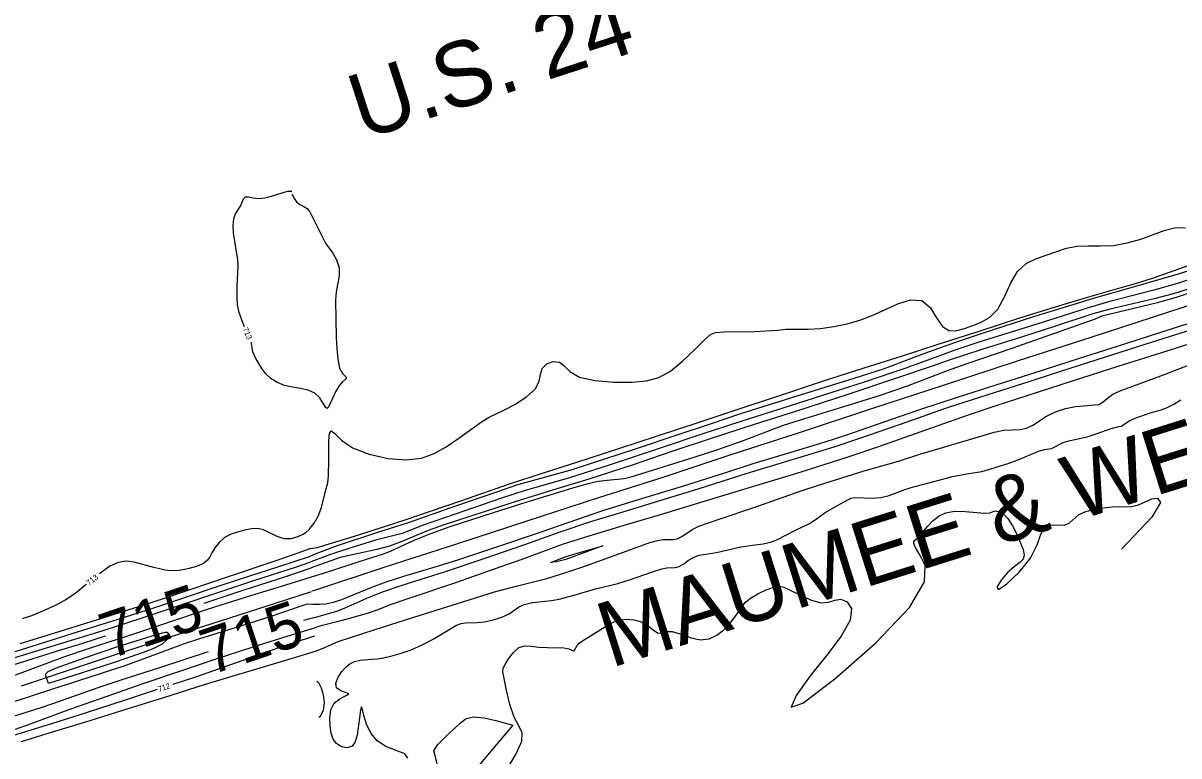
# Model space of a CAD drawing. Extents: x -468548933 to 3387700, y -306089263 to 1207014.
# Drawn here: x 1838882 to 1839713, y 536505 to 537032 of the extents above; entities that cross this region are included whole.
import ezdxf

# ---------------------------------------------------------------- set-up
doc = ezdxf.new("R2010")
doc.units = 0
for name, color, linetype in [('DT_X_Contour_Minor', 7, 'Continuous'), ('Level 14', 7, 'Continuous'), ('Level 19', 7, 'Continuous'), ('Level 40', 7, 'Continuous')]:
    doc.layers.add(name, color=color, linetype=linetype)

msp = doc.modelspace()

# ---------------------------------------------------------------- linework, layer by layer
at = {"layer": 'DT_X_Contour_Minor'}
for points in [[(1839040.98, 536813.8), (1839039.19, 536818.01), (1839037.08, 536824.03), (1839035.91, 536829.55), (1839035.51, 536834.49), (1839035.67, 536842.86), (1839036.26, 536857.84), (1839036.02, 536861.91), (1839034.64, 536870.8), (1839033.04, 536881.32), (1839032.73, 536886.73), (1839033.16, 536891.45), (1839034.49, 536895.05), (1839038, 536900.52), (1839040.26, 536905.73), (1839041.71, 536907.18), (1839043.99, 536907.22), (1839047.12, 536906.53), (1839051, 536906.05), (1839055.49, 536906.49), (1839060.19, 536907.64), (1839071.78, 536911.25), (1839074.81, 536911.39)], [(1839074.93, 536909.12), (1839075.32, 536908.66), (1839076.64, 536906.06), (1839078.31, 536903.58), (1839080.71, 536901.81), (1839083.48, 536900.39), (1839086.01, 536898.74), (1839087.92, 536896.36), (1839099.37, 536873.52), (1839101.8, 536870.42), (1839104.4, 536866.75), (1839107.13, 536861.85), (1839108.89, 536856.24), (1839108.95, 536850.37), (1839106.83, 536838.57), (1839106.37, 536832.92), (1839106.9, 536805.77), (1839107.19, 536798.12), (1839107.9, 536790.35), (1839109.27, 536784.03), (1839111.35, 536780.26), (1839114.26, 536777.3), (1839113.42, 536776.01), (1839111.29, 536774.06), (1839108.69, 536771.1), (1839106.26, 536767), (1839101.41, 536755.82), (1839100.4, 536754.85), (1839099.21, 536755.82), (1839095.01, 536762.54), (1839091.46, 536765.98), (1839086.72, 536768.1), (1839082.13, 536769.09)], [(1839087.34, 536667.91), (1839088.18, 536668.75), (1839091.09, 536672.35), (1839093.97, 536677.39), (1839096.31, 536683.76), (1839099.19, 536695.48), (1839100.43, 536699.91), (1839100.84, 536701.41), (1839101.29, 536706.55), (1839101.45, 536717.89), (1839101.52, 536731.66), (1839101.98, 536736.9), (1839103.22, 536738.98), (1839105.76, 536736.94), (1839110.53, 536732.16), (1839118.62, 536726.62), (1839130.5, 536722.04), (1839144.27, 536719.05), (1839157.47, 536718.03), (1839168.24, 536719.25), (1839177.26, 536722.5), (1839185.86, 536727.48), (1839194.95, 536733.71), (1839211.29, 536745.34), (1839216.76, 536748.63), (1839227.33, 536753.69), (1839235.28, 536757.93), (1839243.66, 536763.29), (1839250.06, 536769.05), (1839252.87, 536774.56), (1839253.69, 536779.54), (1839254.9, 536783.8), (1839258.24, 536787.07), (1839262.89, 536788.81), (1839267.37, 536788.41), (1839270.81, 536785.59), (1839274.86, 536781.51), (1839281.79, 536777.62), (1839293, 536775.12), (1839306.54, 536773.98), (1839319.61, 536773.91), (1839330.11, 536774.76), (1839338.82, 536777.16), (1839347.19, 536781.89), (1839356.2, 536789.25), (1839364.87, 536797.5), (1839371.71, 536804.38), (1839375.95, 536808.24), (1839379.67, 536809.7), (1839385.69, 536810.01), (1839407.63, 536810.45), (1839424.15, 536811.3), (1839430.3, 536811.96), (1839446.38, 536811.93), (1839455.07, 536812.63), (1839464.71, 536813.96), (1839474.39, 536815.95), (1839483.46, 536818.62), (1839492.21, 536821.98), (1839510.74, 536830.3), (1839520.01, 536833.22), (1839527.98, 536832.7), (1839533.94, 536827.58), (1839538.56, 536820.23), (1839542.85, 536813.89), (1839547.54, 536811.01), (1839552.19, 536810.83), (1839558.72, 536812.59), (1839564.7, 536814.62), (1839570.18, 536816.74), (1839576.68, 536820.45), (1839582.81, 536826.52), (1839587.62, 536835.22), (1839591.89, 536844.9), (1839596.78, 536853.43), (1839603.15, 536859.23), (1839610.51, 536862.89), (1839632.22, 536870.38), (1839639.59, 536871.75), (1839647.69, 536872.01), (1839656.53, 536871.88), (1839665.98, 536872.33), (1839675.85, 536874.06), (1839685.57, 536876.79), (1839702.27, 536882.98), (1839709.67, 536885.03), (1839717.78, 536885.23)], [(1839088.05, 536654.13), (1839093.28, 536655.03), (1839099.42, 536656.76), (1839119.97, 536663.21), (1839156.43, 536674.83), (1839174.57, 536680.99), (1839196.38, 536688.56), (1839232.22, 536700.94), (1839261.99, 536710.65), (1839287.94, 536719.11), (1839323.23, 536730.62), (1839367.86, 536745.19), (1839403.81, 536757.02), (1839423.09, 536763.44), (1839455.99, 536774.34), (1839486.57, 536784.19), (1839514.04, 536792.79), (1839539.81, 536801.13), (1839568.56, 536810.46), (1839599.24, 536820.51), (1839632.86, 536830.85), (1839652.16, 536836.58), (1839684.07, 536845.53), (1839694.56, 536849), (1839721.09, 536858.22)], [(1839732.38, 536857.86), (1839712.33, 536851.72), (1839678.35, 536841.85), (1839651.17, 536834.01), (1839633.6, 536828.65), (1839609.2, 536821.09), (1839578.65, 536811.43), (1839554.98, 536803.41), (1839529.99, 536794.42), (1839501.07, 536783.55), (1839479.13, 536776.57), (1839438.19, 536763.75), (1839397.71, 536751.01), (1839376.57, 536743.97), (1839351.9, 536735.79), (1839323.19, 536726.27), (1839275.53, 536710.61), (1839250.45, 536703.59), (1839236.42, 536699.69), (1839222.76, 536695.11), (1839192.75, 536684.6), (1839158.5, 536672.76), (1839136.59, 536665.73), (1839106.13, 536655.6), (1839092.9, 536650.71), (1839088.33, 536648.78)], [(1839743.3, 536855.2), (1839711.86, 536845.01), (1839694.8, 536840.15), (1839663.17, 536832.03), (1839647.78, 536827.48), (1839623.61, 536819.69), (1839595.51, 536810.9), (1839569.87, 536802.82), (1839552.57, 536797.06), (1839537.67, 536791.71), (1839515.8, 536783.7), (1839486.51, 536773.85), (1839462.6, 536766.15), (1839433.37, 536756.94), (1839397.77, 536745.71), (1839369.73, 536736.4), (1839339.74, 536726.36), (1839304.67, 536714.75), (1839273.81, 536704.88), (1839242.84, 536695.91), (1839225.63, 536690.39), (1839192.51, 536679.04), (1839169.32, 536671.09), (1839154.17, 536665.09), (1839142.82, 536662.21), (1839135.1, 536660.22), (1839115.91, 536654.34), (1839102.84, 536649.86), (1839088.54, 536644.59)], [(1839737.01, 536846.82), (1839711.39, 536838.3), (1839696.14, 536834.16), (1839663.45, 536826.37), (1839651.1, 536823.11), (1839623.57, 536814.04), (1839600.5, 536806.5), (1839571.28, 536797.41), (1839547.62, 536789.83), (1839534.88, 536785.3), (1839509.16, 536776.54), (1839475.43, 536765.3), (1839436.47, 536752.64), (1839407.4, 536743.44), (1839377.31, 536733.73), (1839348.29, 536723.97), (1839319.63, 536714.29), (1839288.54, 536704.19), (1839265.62, 536697.07), (1839238.47, 536688.8), (1839213.96, 536680.91), (1839184.45, 536671.21), (1839173.09, 536667.09), (1839154.05, 536659.25), (1839145.16, 536656.02), (1839135.94, 536653.53), (1839109.63, 536647.71), (1839088.76, 536640.4)], [(1839089.1, 536633.79), (1839100.93, 536637.51), (1839123.4, 536644.9), (1839140.76, 536650.3), (1839145.78, 536652.35), (1839162.88, 536660.12), (1839174.98, 536665.09), (1839188.84, 536670.11), (1839219.26, 536679.99), (1839240.29, 536686.5), (1839276.32, 536697.59), (1839288.16, 536701.1), (1839295.16, 536702.63), (1839301.76, 536703.46), (1839313.87, 536704.64), (1839319.8, 536705.97), (1839334.22, 536710.52), (1839364.24, 536719.85), (1839381.43, 536725.41), (1839400.93, 536732.53), (1839428.5, 536742.92), (1839443.82, 536747.87), (1839468.73, 536755.47), (1839498.35, 536764.48), (1839517.71, 536771.34), (1839546.63, 536782.33), (1839560.63, 536787.34), (1839592.34, 536798.05), (1839622.21, 536808.64), (1839652.91, 536819.5), (1839657.6, 536821.56), (1839663.49, 536823.17), (1839697.6, 536831.34), (1839711.19, 536834.95), (1839727.36, 536840.36)], [(1839729.89, 536819.24), (1839698.29, 536809.16), (1839669.22, 536799.83), (1839640.51, 536790.58), (1839610.08, 536780.86), (1839576.7, 536770.23), (1839552.73, 536762.68), (1839526.26, 536754.01), (1839506.2, 536746.95), (1839473.16, 536735.44), (1839458.37, 536730.77), (1839433.8, 536723.31), (1839406.57, 536715.04), (1839386.03, 536708.51), (1839354.92, 536698.65), (1839324.1, 536689.14), (1839298.32, 536681.28), (1839279.68, 536674.98), (1839249.26, 536664.36), (1839225.71, 536656.35), (1839194.83, 536646.07), (1839180.22, 536641.5), (1839155.29, 536634.09), (1839142.5, 536629.96), (1839132.21, 536626.18), (1839110.7, 536617.41), (1839104.7, 536615.49), (1839099.33, 536614.3), (1839094.74, 536613.89), (1839090.11, 536614.04)], [(1839090.61, 536604.46), (1839107.89, 536609.42), (1839113.29, 536611.6), (1839130.64, 536619.23), (1839141.69, 536623.63), (1839153.47, 536627.69), (1839185.48, 536637.69), (1839214, 536647.32), (1839242.42, 536657.02), (1839268.01, 536666.15), (1839289.93, 536673.57), (1839308.47, 536679.3), (1839341.34, 536689.19), (1839367.06, 536697.24), (1839401.64, 536708.13), (1839433.38, 536717.74), (1839465.1, 536727.5), (1839483.4, 536733.55), (1839517.42, 536745.43), (1839547.98, 536756.07), (1839581.11, 536766.7), (1839605.93, 536774.65), (1839628.81, 536781.96), (1839653.49, 536789.88), (1839688.58, 536801.15), (1839722.89, 536812.07)], [(1839732.14, 536805.15), (1839704.34, 536796.31), (1839669, 536785.07), (1839636.87, 536774.79), (1839610.98, 536766.44), (1839581.26, 536756.85), (1839561.43, 536750.17), (1839530.78, 536739.29), (1839496.96, 536727.3), (1839475.48, 536720.2), (1839441.09, 536709.22), (1839422, 536703.41), (1839391.78, 536694.31), (1839358.85, 536684.18), (1839339.15, 536678.11), (1839316.18, 536671.4), (1839288.47, 536663.23), (1839269.37, 536657.04), (1839240.26, 536646.38), (1839214.9, 536637.35), (1839193.26, 536629.84), (1839158.41, 536617.97), (1839146.39, 536613.96), (1839135.94, 536609.87), (1839129.01, 536607.48), (1839111.1, 536602.45), (1839095.14, 536598.26), (1839090.99, 536597)], [(1839082.13, 536769.09), (1839081.18, 536769.29), (1839075.37, 536770.26), (1839069.76, 536771.62), (1839064.58, 536773.6), (1839060.04, 536776.35), (1839056.27, 536779.88), (1839053.23, 536783.8), (1839049.04, 536790.83), (1839046.92, 536795.63), (1839046.28, 536798.79), (1839045.91, 536801.67), (1839045.59, 536802.72)], [(1839091.84, 536580.45), (1839097.49, 536582.55), (1839108.3, 536587.26), (1839134.92, 536596.07), (1839162.75, 536604.87), (1839193.97, 536614.73), (1839220.8, 536623.03), (1839235.3, 536626.9), (1839258.24, 536632.76), (1839271.3, 536636.66), (1839286.45, 536641.75), (1839316.22, 536652.63), (1839332.51, 536658.53), (1839337.82, 536660.1), (1839341.99, 536660.79), (1839348.92, 536660.69), (1839352.12, 536661.25), (1839355.38, 536662.97), (1839362.91, 536667.99), (1839367.71, 536670.21), (1839383.1, 536675.51), (1839407.99, 536684.08), (1839441.92, 536696.04), (1839453.61, 536699.91), (1839486.55, 536710), (1839511.37, 536717.19), (1839526.68, 536722.02), (1839561.54, 536732.53), (1839579.99, 536738.04), (1839587.11, 536739.45), (1839598.66, 536739.93), (1839603.43, 536740.73), (1839607.81, 536742.91), (1839617.68, 536749.48), (1839624.2, 536752.54), (1839631.42, 536754.93), (1839638.63, 536756.42), (1839655.26, 536757.9), (1839658.58, 536759.75), (1839661.58, 536762.36), (1839665.31, 536765.17), (1839670.7, 536767.79), (1839700.05, 536778.41), (1839724.24, 536787.73)], [(1839539.54, 536703.23), (1839549.78, 536706.07), (1839561.87, 536708.14), (1839571.12, 536709.74), (1839578.5, 536711.82), (1839590.12, 536715.4), (1839596.62, 536717.75), (1839612.64, 536724.57), (1839616.16, 536725.38), (1839621.24, 536726.18), (1839629.72, 536730.53), (1839634.68, 536731.84), (1839647.08, 536734.67), (1839653.48, 536736.76), (1839664.15, 536740.68), (1839669.85, 536741.92), (1839671.35, 536742.26), (1839676.99, 536745.9), (1839681.54, 536747.92), (1839692.25, 536751.74), (1839700.19, 536754.03), (1839704.08, 536755.5), (1839708.79, 536757.84), (1839714.36, 536761.19)], [(1839158.31, 536503.49), (1839156.17, 536506.42), (1839142.44, 536511.68), (1839136.37, 536515.79), (1839131.96, 536521.04), (1839128.93, 536527.1), (1839126.99, 536533.41), (1839125.8, 536538.41), (1839124.98, 536540.35), (1839124.2, 536538.03), (1839121.8, 536520.03), (1839120.48, 536515.11), (1839118.21, 536511.91), (1839114.72, 536510.84), (1839110.72, 536511.63), (1839107.13, 536513.84), (1839104.69, 536517.12), (1839103.27, 536521.35), (1839102.52, 536526.49), (1839102.26, 536532.34), (1839103, 536538.16), (1839105.41, 536543.05), (1839109.65, 536546.35), (1839113.9, 536548.36), (1839115.87, 536549.56), (1839114.05, 536550.49), (1839110.25, 536551.74), (1839107.09, 536553.93), (1839106.57, 536557.42), (1839108.21, 536561.63), (1839110.88, 536565.7), (1839113.71, 536568.96), (1839116.7, 536571.34), (1839120.11, 536572.92), (1839124.06, 536573.83), (1839132.52, 536574.56), (1839136.49, 536574.89), (1839140.77, 536575.53), (1839146.07, 536576.73), (1839152.86, 536578.7), (1839160.65, 536581.45), (1839168.76, 536584.97), (1839176.5, 536589.1), (1839193.31, 536598.98), (1839196.65, 536600.18), (1839199.88, 536600.66), (1839208.19, 536600.92), (1839213.58, 536601.52), (1839219.75, 536602.87), (1839225.92, 536604.86), (1839231.15, 536607.24), (1839238.07, 536612.14), (1839242.12, 536614.04), (1839247.96, 536615.27), (1839261.58, 536616.8), (1839267.29, 536617.76), (1839277.12, 536620.43), (1839293.34, 536625.18), (1839309.34, 536629.04), (1839318.57, 536632.05), (1839333.5, 536637.22), (1839341.11, 536639.64), (1839344.65, 536640.32), (1839350.61, 536640.51), (1839353.55, 536641.32), (1839356.81, 536643.3), (1839360.34, 536645.86), (1839364.04, 536648.11), (1839367.83, 536649.4), (1839380.4, 536651.41), (1839397.84, 536655.51), (1839408.1, 536656.91), (1839413.87, 536657.68), (1839419.24, 536658.84), (1839423.74, 536660.59), (1839437.16, 536667.52), (1839447.26, 536672.33), (1839451.28, 536674.85), (1839458.62, 536680.09), (1839467.36, 536685.25), (1839476.95, 536690.48), (1839480.59, 536691), (1839492.12, 536690.54), (1839498.55, 536690.86), (1839504.46, 536692.31), (1839515.84, 536696.74), (1839522.06, 536698.64), (1839539.54, 536703.23)], [(1839540.44, 536677.63), (1839545.33, 536679.96), (1839551.48, 536681.04), (1839559.12, 536680.85), (1839573.32, 536679.59), (1839577.06, 536679.99), (1839580.79, 536681.36), (1839583.29, 536680.95), (1839586.47, 536679.2), (1839589.93, 536675.79), (1839593.29, 536670.62), (1839596.35, 536664.53), (1839600.86, 536653.59), (1839601.7, 536649.65), (1839601.02, 536646.58), (1839598.53, 536644.1), (1839594.63, 536641.33), (1839589.87, 536637.23), (1839585.07, 536631.45), (1839582.11, 536626.3), (1839583.12, 536624.74), (1839589.3, 536628.86), (1839598.15, 536637.14), (1839606.22, 536647.18), (1839611.01, 536656.78), (1839613.71, 536664.65), (1839616.43, 536669.7), (1839620.72, 536671.36), (1839630.75, 536671.1), (1839634.36, 536672.73), (1839640.76, 536678.36), (1839645.27, 536680.5), (1839650.52, 536681.94), (1839660.73, 536683.7), (1839665.27, 536684.2), (1839669.72, 536684.39), (1839674.26, 536684.31), (1839678.94, 536684.48), (1839683.77, 536685.55), (1839693.43, 536689.96), (1839697.61, 536690.53), (1839699.7, 536687.43), (1839693.5, 536676.68), (1839671.62, 536653.81)], [(1839221.34, 536481.34), (1839236.24, 536506.39), (1839240.37, 536515.51), (1839240.69, 536521.6), (1839238.3, 536526.56), (1839234.84, 536532.83), (1839231.72, 536542), (1839229.28, 536552.2), (1839226.77, 536565.52), (1839226.95, 536568.12), (1839228.29, 536570.7), (1839230.85, 536574.85), (1839234.33, 536579.53), (1839238.3, 536583.09), (1839242.5, 536584.32), (1839247.13, 536583.96), (1839252.53, 536583.21), (1839258.81, 536582.98), (1839270.54, 536582.88), (1839274.18, 536582.14), (1839277.55, 536580.69), (1839278.28, 536580.99), (1839280.08, 536584.46), (1839281.68, 536586.05), (1839284.7, 536588.24), (1839303.72, 536599.93), (1839306.84, 536601.59), (1839310.44, 536602.69), (1839315.3, 536603.28), (1839320.91, 536603.02), (1839326.44, 536601.49), (1839331.21, 536598.58), (1839335.16, 536595.4), (1839338.4, 536593.39), (1839341.15, 536593.46), (1839344.18, 536594.43), (1839348.38, 536594.59), (1839354.35, 536592.81), (1839361.4, 536590.24), (1839368.56, 536588.6), (1839375.01, 536589.22), (1839380.67, 536591.8), (1839385.62, 536595.69), (1839389.93, 536600.24), (1839393.56, 536604.89), (1839398.73, 536612.61), (1839401.18, 536615.59), (1839404.78, 536618.5), (1839410.1, 536621.59), (1839416.15, 536624.45), (1839421.52, 536626.5), (1839425.34, 536627.24), (1839428.71, 536626.53), (1839447.96, 536617.29), (1839455.33, 536615.25), (1839460.95, 536615.65), (1839465.41, 536617.13), (1839469.73, 536617.72), (1839474.38, 536615.79), (1839477.49, 536610.82), (1839476.58, 536602.62), (1839470.06, 536591.2), (1839459.61, 536577.49), (1839447.79, 536562.63), (1839437.61, 536548.5), (1839434.03, 536540.04), (1839442.48, 536542.92), (1839465.59, 536560.42), (1839494.89, 536586.28), (1839519.14, 536611.87), (1839529.96, 536630.34), (1839530.54, 536642.05), (1839526.93, 536649.18), (1839524.12, 536653.65), (1839522.7, 536656.37), (1839522.21, 536658.01), (1839522.21, 536659.11), (1839522.94, 536660.28), (1839524.35, 536661.25), (1839526.02, 536662.98), (1839532.27, 536670.2), (1839536.23, 536674.27), (1839540.44, 536677.63)], [(1839087.34, 536667.91), (1839084.5, 536665.19), (1839083.4, 536664.46), (1839078.52, 536662.35), (1839074.27, 536661.25), (1839069.38, 536661.25), (1839064.3, 536662.93), (1839054.63, 536667.64), (1839050.39, 536668.58), (1839046.25, 536668.41), (1839041.77, 536667.56), (1839036.67, 536666.33), (1839031.39, 536664.57), (1839026.51, 536662.05), (1839022.54, 536658.64), (1839019.53, 536654.83), (1839017.42, 536651.2), (1839015.99, 536648.22), (1839014.33, 536645.76), (1839011.36, 536643.53), (1839006.36, 536641.36), (1839000.13, 536639.52), (1838993.84, 536638.39), (1838988.43, 536638.2), (1838983.8, 536638.74), (1838975.56, 536640.68), (1838961.52, 536644.38), (1838955.85, 536645.06), (1838949.92, 536644.27), (1838943.99, 536641.48), (1838938.44, 536637.54), (1838936.53, 536635.99)], [(1839298.64, 536656.26), (1839271.95, 536646.38), (1839265.29, 536644.72), (1839261.24, 536644.11), (1839262.99, 536645), (1839272.3, 536648.56), (1839277.72, 536650.23), (1839298.64, 536656.26)], [(1838864.14, 536576.63), (1838897.2, 536586.91), (1838921.58, 536594.51), (1838949.29, 536603.18), (1838976.45, 536611.79), (1838990.85, 536616.56), (1839018.28, 536625.98), (1839037.31, 536632.27), (1839064.86, 536641.14), (1839088.33, 536648.78)], [(1839088.05, 536654.13), (1839087.08, 536653.8), (1839082.59, 536652.09), (1839063.39, 536645.42), (1839026.86, 536633.03), (1839015.66, 536629.31), (1838983.78, 536618.39), (1838966.15, 536612.73), (1838938.13, 536603.87), (1838908.12, 536594.54), (1838879.33, 536585.63)], [(1838688.74, 536514.52), (1838718.58, 536524.39), (1838743.72, 536532.32), (1838773.24, 536541.87), (1838802.31, 536551.47), (1838824.64, 536558.91), (1838853.42, 536568.62), (1838878.19, 536576.43), (1838907.11, 536585.41), (1838939.11, 536595.34), (1838967.33, 536604.29), (1838994.62, 536613.53), (1839021.67, 536622.69), (1839048.26, 536631.35), (1839076.86, 536640.64), (1839088.54, 536644.59)], [(1839011.98, 536614.97), (1839040.6, 536624.4), (1839069.92, 536633.93), (1839088.76, 536640.4)], [(1838911.76, 536576.5), (1838928.64, 536582.29), (1838957.59, 536591.58), (1838985.76, 536601.05), (1839015, 536610.8), (1839045.42, 536620.4), (1839073.64, 536629.15), (1839089.1, 536633.79)], [(1838927.21, 536628.43), (1838925.9, 536627.36), (1838923.69, 536625.81), (1838922.98, 536624.96), (1838921.06, 536623.29), (1838917.36, 536620.61), (1838911.86, 536617.14), (1838904.68, 536613.24), (1838896.19, 536609.31), (1838887.77, 536605.9), (1838881.04, 536603.58)], [(1839090.11, 536614.04), (1839086.33, 536614.13), (1839083.64, 536613.45), (1839059.71, 536605.41), (1839034.93, 536597.29), (1839007.74, 536588.9), (1838997.52, 536585.61), (1838973.06, 536576.58), (1838954.01, 536569.64), (1838928.91, 536561.52), (1838902.11, 536552.91), (1838874.15, 536543.74)], [(1839090.61, 536604.46), (1839083.28, 536602.36)], [(1838875.1, 536570.9), (1838905.77, 536580.41), (1838924.63, 536586.22), (1838941, 536591.3)], [(1839090.99, 536597), (1839071.35, 536591), (1839046.88, 536583.28), (1839019.49, 536574.3), (1838995.45, 536566.18), (1838967.11, 536556.52), (1838941.86, 536547.83), (1838915.62, 536538.53), (1838886.81, 536527.91), (1838875.94, 536524.06)], [(1838899.92, 536557.22), (1838898.05, 536562.87), (1838897.94, 536564.18), (1838899.68, 536565.69), (1838904.97, 536568.08), (1838926.53, 536575.93), (1838950.49, 536584.03), (1838979.92, 536593.04), (1838983.81, 536594.13), (1838985.35, 536594.16), (1838985.88, 536593.2), (1838986.24, 536591.34), (1838985.35, 536588.72), (1838981.68, 536585.49), (1838974.39, 536581.87), (1838965.35, 536578.34), (1838946.37, 536571.87), (1838917.4, 536562.73), (1838899.92, 536557.22)], [(1839091.29, 536591.18), (1839087.29, 536590.05), (1839070.4, 536584.42), (1839039.58, 536573.56), (1839005.65, 536561.73), (1838989.45, 536556.43)], [(1839014.65, 536579.87), (1838996.57, 536573.78), (1838979.79, 536568.27), (1838951.86, 536559.49), (1838935.35, 536553.94), (1838909.12, 536544.58), (1838894.39, 536539.53), (1838866.05, 536530.84)], [(1838868.66, 536560.47), (1838887.23, 536567.43), (1838911.76, 536576.5)], [(1838880.39, 536515.41), (1838902.03, 536522.1), (1838929.99, 536530.58), (1838957.11, 536539.02), (1838982.19, 536546.68), (1839012.88, 536556.54), (1839032.11, 536562.45), (1839061.65, 536571.27), (1839091.84, 536580.42)], [(1839092.95, 536558.88), (1839094.13, 536557.75), (1839096.08, 536554.08), (1839097.51, 536549.15), (1839098.15, 536543.34), (1839097.5, 536537.63), (1839095.06, 536533.15), (1839094.3, 536532.74)], [(1838978.05, 536552.69), (1838954.94, 536545.06), (1838927.76, 536536.35), (1838902.05, 536528.06), (1838871.53, 536518.76)], [(1839179.37, 536499.42), (1839178.03, 536505.27), (1839176.96, 536508.76), (1839179.87, 536513.33), (1839185.56, 536518.86), (1839196.2, 536528.86), (1839200.37, 536531.93), (1839205.74, 536533.18), (1839213.35, 536532.46), (1839221.65, 536530.61), (1839233.88, 536527.11)], [(1839233.88, 536527.11), (1839215.73, 536505.57), (1839192.85, 536478.46)]]:
    msp.add_lwpolyline(points, dxfattribs=at)
at = {"layer": 'Level 14'}
for points in [[(1840215.68, 536991.19), (1840166.74, 536975.14), (1840115.14, 536958.34), (1840064.93, 536942), (1840016.99, 536926.47), (1839968.63, 536910.49), (1839916.59, 536893.5), (1839858.06, 536874.3), (1839806.25, 536857.4), (1839756.25, 536840.84), (1839704.68, 536824.11), (1839650.44, 536806.37), (1839596.54, 536788.99), (1839543.36, 536771.52), (1839493.31, 536755.09), (1839439.8, 536737.54), (1839390.59, 536721.57), (1839342.49, 536705.66), (1839295.47, 536690.59), (1839243.91, 536673.81), (1839194, 536657.55), (1839141.15, 536640.47), (1839091.29, 536624.06), (1839089.63, 536623.52)], [(1838880.4, 536555.5), (1838950.35, 536578.67), (1838987.43, 536590.66), (1839023.55, 536602.19), (1839063.82, 536615.2), (1839088.99, 536623.32)]]:
    msp.add_lwpolyline(points, dxfattribs=at)

# ---------------------------------------------------------------- texts
at = {"layer": 'Level 19'}
for s, height, rotation, p in [('713', 4, 293.24553, (1839039.45, 536812.3)), ('713', 4, 39.0528, (1838929.07, 536627.36)), ('715', 33, 18.74145, (1838943.86, 536574.51)), ('715', 33, 18.4607, (1839016.06, 536562.97)), ('712', 4, 18.12266, (1838979.4, 536551.03))]:
    msp.add_text(s, height=height, rotation=rotation, dxfattribs=at).set_placement(p)
at = {"layer": 'Level 40'}
for s, rotation, p in [('U.S. 24', 17.98637, (1839125.75, 536947.98)), ('MAUMEE & WESTERN RR', 17.51707, (1839304.22, 536568.16))]:
    msp.add_text(s, height=46.8, rotation=rotation, dxfattribs=at).set_placement(p)

doc.saveas('drawing.dxf')
